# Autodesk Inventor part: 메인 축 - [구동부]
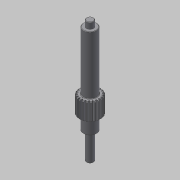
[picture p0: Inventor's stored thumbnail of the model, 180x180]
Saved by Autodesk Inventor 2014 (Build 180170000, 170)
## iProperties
Created: 2016-02
Part Number: 메인 축 - [구동부]
Material: 일반
Document SubType Name: Modeling
Categories: <?xml version="1.0" encoding="UTF-16"?> <MemberInstance><Categories><FamilyTemplate><FamilyTemplateParameter ValueType="xs:double" Id="1" ObjectReferenceKey="da
Density: 1 g/cm^3
Mass: 23.8554 g
Surface Area: 82.0529 cm^2
Volume: 23.8554 cm^3
Appearance: 기본값
Author: mdu
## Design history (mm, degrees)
sketch "Sketch1"
  geometry: C1 r 12 at (0, 0)
  constraints: 1 centre point
  dimensions: "d0" = 24 diameter of C1 (= da_da)
extrude "Extrusion1" new body sketch "Sketch1" distance "d1" = 20 (= da_b); taper "d2" = 0 deg
workplane "Work Plane2"
feature "피치 지름" dims "d4" = 10, "d5" = 0
workplane "Work Plane8"
workplane "Work Plane9"
chamfer "모따기1" distance "d49" = 1; stored, may be unused: second distance "d50" = 2, angle "d51" = 45 deg
sketch "스케치3"
  geometry: C1 r 7.5 at (0, 0); 1 further point
  constraints: 1 centre point, 1 coincident
  dimensions: "d52" = 15 diameter of C1
extrude "돌출2" join sketch "스케치3" distance "d53" = 66; taper "d54" = 0 deg
sketch "스케치4"
  geometry: C1 r 4 at (0, 0); 1 further point
  constraints: 1 centre point, 1 coincident
  dimensions: "d55" = 8 diameter of C1
extrude "돌출3" join sketch "스케치4" distance "d56" = 7; taper "d57" = 0 deg
sketch "스케치5"
  geometry: C1 r 7.5 at (0, 0) reference; C2 r 7.5 at (0, 0) reference; 1 further point
extrude "돌출4" join sketch "스케치5" distance "d62" = 16; taper "d63" = 0 deg
sketch "스케치6"
  geometry: C1 r 4 at (0, 0); 1 further point
  constraints: 1 centre point, 1 coincident
  dimensions: "d64" = 8 diameter of C1
extrude "돌출5" join sketch "스케치6" distance "d65" = 30; taper "d66" = 0 deg
chamfer "모따기2" distance "d58" = 0.5; stored, may be unused: second distance "d59" = 2, angle "d60" = 45 deg
fillet "모깎기1" dims "d61" = 0.5
feature "스퍼 기어" dims "da_b" = 20, "da_d" = 22, "da_aw" = 31, "da_da" = 24, "da_df" = 19.5, "da_dw" = 22, angle "da_beta" = 0 deg, "da_lefttooth" = 0, "da_righttooth" = 0
sketch "스케치7" dims "d68" = 18
  geometry: C1 r 0.25 at (0, -9); 2 further points
  constraints: 2 vertical alignment, 1 centre point, 1 coincident, 2 other
  dimensions: "d67" = 0.5 diameter of C1
extrude "돌출6" join sketch "스케치7" distance "d69" = 0.3; taper "d70" = 0 deg
body "Solid1"
sketch "Sketch2"
  geometry: C1 r 12 at (0, 0) reference; C2 r 11 at (0, 0)
  constraints: 1 centre point, 1 coincident
  dimensions: "d3" = 22 diameter of C2 (= da_dw)
body "Srf1"
node "투영된 루프1"
other parameters: "d16" = 31 (= da_aw), "d17" = 0, "d34" = 1.428 (computed from da_z), "d39" = 0, "d41" = 0, "d43" = 31 (= da_aw), "d46" = 31 (= da_aw), "d47" = 0, "d48" = 0
